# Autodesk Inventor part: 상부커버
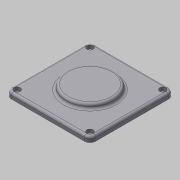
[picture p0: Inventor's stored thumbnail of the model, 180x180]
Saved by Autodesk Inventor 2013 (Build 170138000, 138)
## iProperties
Created: 2018-09
Part Number: 상부커버
Document SubType Name: Modeling
Density: 2.71 g/cm^3
Material: 알루미늄 6061
Mass: 249.406 g
Surface Area: 254.001 cm^2
Volume: 92.0316 cm^3
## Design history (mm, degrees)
sketch "스케치5"
  geometry: L1 (-52.5, -52.5)-(52.5, -52.5); L2 (52.5, -52.5)-(52.5, 52.5); L3 (52.5, 52.5)-(-52.5, 52.5); L4 (-52.5, 52.5)-(-52.5, -52.5); L5 (-52.5, -52.5)-(52.5, 52.5); L6 (52.5, -52.5)-(-52.5, 52.5); 1 further point
  constraints: 12 end point, 2 midpoint, 2 parallel, 1 horizontal, 1 perpendicular
  dimensions: "d35" = 105 distance of L3.end L2.end; "d36" = 105 distance of L2.end L1.end
extrude "돌출4" new body sketch "스케치5" distance "d37" = 7; taper "d38" = 0 deg
fillet "모깎기4" dims "d39" = 7
sketch "스케치2"
  geometry: C1 r 30 at (0, 0); 2 further points
  constraints: 2 coincident, 1 centre point
  dimensions: "d4" = 60 diameter of C1
extrude "돌출3" join sketch "스케치2" distance "d5" = 6; taper "d6" = 0 deg
fillet "모깎기1" dims "d7" = 3
sketch "스케치4"
  geometry: L1 (52.5, -45.5)-(52.5, 45.5) reference; L2 (-45.5, -52.5)-(45.5, -52.5) reference; L3 (-52.5, 45.5)-(-52.5, -45.5) reference; L4 (45.5, 52.5)-(-45.5, 52.5) reference; A1 r 7 centre (45.5, 45.5) between (52.5, 45.5) and (45.5, 52.5) reference; A2 r 7 centre (45.5, -45.5) between (45.5, -52.5) and (52.5, -45.5) reference; A3 r 7 centre (-45.5, -45.5) between (-52.5, -45.5) and (-45.5, -52.5) reference; A4 r 7 centre (-45.5, 45.5) between (-45.5, 52.5) and (-52.5, 45.5) reference; 4 further points
  constraints: 4 coincident
hole "구멍3" sketch "스케치4" at (-45.5, 45.5), (-45.5, -45.5), (45.5, -45.5), (45.5, 45.5) diameter "d43" = 4.5; stored, may be unused: countersink angle "d47" = 90 deg, drill point angle "d49" = 118 deg; dims "d44" = 6, "d45" = 8, "d46" = 4.4, "d48" = 8
fillet "모깎기3" dims "d19" = 3
node "솔리드1"
node "솔리드2"
node "투영된 루프2"
